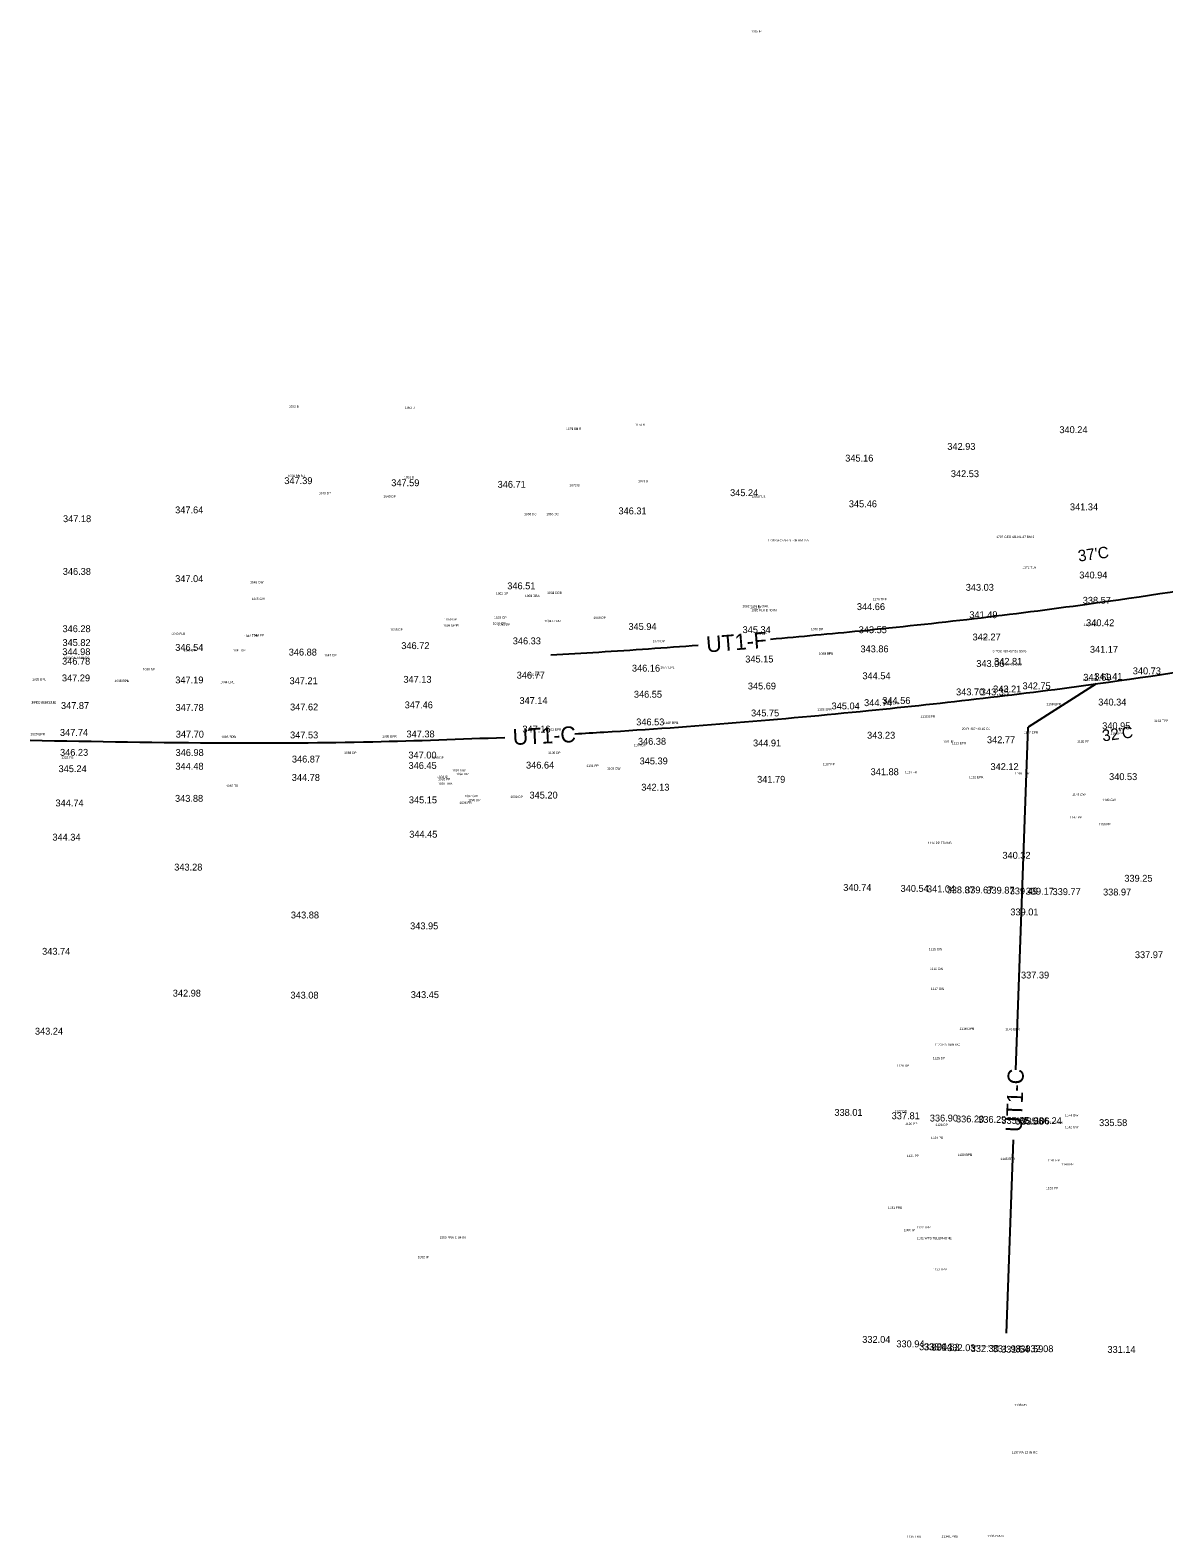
# Model space of a CAD drawing. Extents: x 49683 to 58852, y 49596 to 54801.
# Drawn here: x 50560 to 51054, y 49596 to 50254 of the extents above; entities that cross this region are included whole.
import ezdxf

# ---------------------------------------------------------------- set-up
doc = ezdxf.new("R2010")
doc.units = 0
for name, color, linetype in [('Level 2', 7, 'Continuous'), ('Level 32', 7, 'Continuous'), ('Level 48', 7, 'Continuous'), ('Level 51', 7, 'Continuous'), ('Level 53', 7, 'Continuous'), ('Level 56', 7, 'Continuous'), ('Level 58', 7, 'Continuous'), ('Level 59', 7, 'Continuous'), ('Level 61', 7, 'Continuous'), ('Level 62', 7, 'Continuous')]:
    doc.layers.add(name, color=color, linetype=linetype)

msp = doc.modelspace()

# ---------------------------------------------------------------- linework, layer by layer
at = {"layer": 'Level 2'}
for p, q in [((51025.02, 49968.44), (50995.33, 49949.54)), ((50989.95, 49800.05), (50995.33, 49949.54)), ((50985.82, 49685.22), (50988.85, 49769.48))]:
    msp.add_line(p, q, dxfattribs=at)
for points in [[(50882.95, 49988.03), (50922.2, 49991.68), (51021.03, 50003.3), (51093.49, 50014.19), (51156.12, 50024.93), (51216.22, 50037.32)], [(50787.09, 49981.18), (50808.05, 49982.38), (50851.37, 49985.39)], [(50797.5, 49946.69), (50810.2, 49947.44), (50925.67, 49956.85), (51025.68, 49968.6), (51099.51, 49979.7)], [(50559.97, 49943.89), (50644.94, 49942.73), (50709.41, 49943.24), (50766.95, 49945.13)]]:
    msp.add_spline(points, degree=3, dxfattribs=at)

# ---------------------------------------------------------------- texts
for s, rotation, p in [('UT1-F', 4.55325, (50855.13, 49982.17)), ('UT1-C', 2.65952, (50770.61, 49941.8)), ('UT1-C', 87.93828, (50992.47, 49772.85))]:
    msp.add_text(s, height=7, rotation=rotation, dxfattribs=at).set_placement(p)
at = {"layer": 'Level 32'}
for s, p in [('340.24', (51008.91, 50077.89)), ('342.93', (50960.03, 50070.59)), ('345.16', (50915.5, 50065.48)), ('347.39', (50670.83, 50055.65)), ('347.59', (50717.47, 50054.73)), ('346.71', (50763.88, 50054.05)), ('342.53', (50961.58, 50058.69)), ('345.24', (50865.28, 50050.4)), ('347.64', (50623.21, 50042.89)), ('346.31', (50816.58, 50042.47)), ('345.46', (50917.07, 50045.54)), ('341.34', (51013.52, 50044.21)), ('347.18', (50574.31, 50039.05)), ('346.38', (50574.2, 50016.05)), ('340.94', (51017.59, 50014.48)), ('347.04', (50623.23, 50012.89)), ('346.51', (50768.09, 50009.75)), ('343.03', (50968.07, 50009.11)), ('344.66', (50920.59, 50000.68)), ('338.57', (51019.11, 50003.45)), ('341.49', (50969.64, 49997.16)), ('346.28', (50574.08, 49991.05)), ('345.94', (50820.93, 49992.01)), ('345.34', (50870.73, 49990.64)), ('343.55', (50921.38, 49990.61)), ('342.27', (50971.05, 49987.44)), ('340.42', (51020.59, 49993.66)), ('344.98', (50573.98, 49981.03)), ('345.82', (50574.05, 49985.01)), ('346.54', (50623.26, 49982.89)), ('346.88', (50672.76, 49980.85)), ('346.72', (50721.86, 49983.66)), ('346.33', (50770.48, 49985.74)), ('343.86', (50922.14, 49982.24)), ('341.17', (51022.24, 49982.06)), ('346.78', (50573.89, 49976.87)), ('345.15', (50871.9, 49977.81)), ('343.06', (50972.67, 49975.85)), ('342.81', (50980.44, 49976.81)), ('347.29', (50573.83, 49969.57)), ('347.19', (50623.27, 49968.69)), ('347.21', (50673.12, 49968.35)), ('347.13', (50722.77, 49968.96)), ('346.77', (50772.2, 49970.78)), ('346.16', (50822.47, 49973.84)), ('344.54', (50922.99, 49970.51)), ('341.69', (51019.34, 49969.86)), ('341.41', (51024.17, 49970.24)), ('340.73', (51040.93, 49972.66)), ('346.55', (50823.31, 49962.45)), ('345.69', (50873.03, 49966.05)), ('343.70', (50963.85, 49963.47)), ('343.35', (50974.64, 49963.46)), ('343.21', (50980.03, 49964.75)), ('342.75', (50992.84, 49966.12)), ('347.87', (50573.41, 49957.52)), ('347.78', (50623.39, 49956.71)), ('347.62', (50673.34, 49956.89)), ('347.46', (50723.36, 49957.81)), ('347.14', (50773.39, 49959.71)), ('345.04', (50909.55, 49957.35)), ('344.74', (50923.73, 49958.78)), ('344.56', (50931.67, 49959.72)), ('340.34', (51025.87, 49959.04)), ('346.53', (50824.33, 49950.37)), ('345.75', (50874.42, 49954.28)), ('340.95', (51027.59, 49948.67)), ('347.74', (50572.97, 49945.78)), ('347.70', (50623.49, 49945.03)), ('347.53', (50673.34, 49944.69)), ('347.38', (50724.13, 49945.12)), ('347.16', (50774.68, 49947.26)), ('346.38', (50825.08, 49941.92)), ('343.23', (50925.03, 49944.57)), ('342.77', (50977.33, 49942.59)), ('346.23', (50573, 49937.1)), ('346.98', (50623.4, 49937.03)), ('347.00', (50724.97, 49935.93)), ('344.91', (50875.28, 49941.19)), ('345.24', (50572.36, 49929.97)), ('344.48', (50623.33, 49931.03)), ('346.87', (50674.14, 49934.17)), ('346.45', (50725.02, 49931.37)), ('346.64', (50776.27, 49931.53)), ('345.39', (50825.82, 49933.35)), ('341.88', (50926.58, 49928.64)), ('342.12', (50978.87, 49930.88)), ('344.78', (50674.09, 49926.14)), ('342.13', (50826.54, 49921.89)), ('341.79', (50877.07, 49925.34)), ('340.53', (51030.6, 49926.5)), ('344.74', (50571.02, 49915.03)), ('343.88', (50623.16, 49917.03)), ('345.15', (50725.16, 49916.37)), ('345.20', (50777.79, 49918.45)), ('344.34', (50569.67, 49900.09)), ('344.45', (50725.31, 49901.37)), ('340.32', (50984.07, 49892.18)), ('343.28', (50622.82, 49887.03)), ('339.25', (51037.25, 49882.15)), ('340.74', (50914.65, 49878.13)), ('340.54', (50939.65, 49877.73)), ('341.04', (50951.16, 49877.54)), ('338.87', (50959.74, 49877.08)), ('339.67', (50967.78, 49877.08)), ('339.87', (50977.07, 49876.94)), ('339.49', (50987.24, 49876.62)), ('339.17', (50994.24, 49876.51)), ('339.77', (51005.95, 49876.32)), ('338.97', (51027.96, 49876.16)), ('343.88', (50673.7, 49866.14)), ('339.01', (50987.53, 49867.47)), ('343.95', (50725.71, 49861.38)), ('343.74', (50565.19, 49850.29)), ('337.97', (51041.86, 49848.81)), ('337.39', (50992.18, 49839.94)), ('342.98', (50622.18, 49832.04)), ('343.08', (50673.48, 49831.14)), ('343.45', (50726.01, 49831.38)), ('343.24', (50562.05, 49815.43)), ('338.01', (50910.79, 49780)), ('337.81', (50935.75, 49778.53)), ('336.90', (50952.4, 49777.54)), ('336.20', (50963.82, 49777.13)), ('336.29', (50973.51, 49776.95)), ('335.85', (50983.62, 49776.51)), ('335.06', (50989.67, 49776.21)), ('335.06', (50992.41, 49776.24)), ('336.24', (50997.71, 49776.38)), ('335.58', (51026.25, 49775.53)), ('332.04', (50922.93, 49680.95)), ('330.94', (50937.8, 49679.02)), ('333.04', (50947.72, 49677.75)), ('333.04', (50949.71, 49677.68)), ('331.53', (50953.11, 49677.56)), ('332.03', (50960.03, 49677.33)), ('332.30', (50970.24, 49676.98)), ('331.98', (50979.85, 49676.89)), ('331.54', (50983.5, 49676.65)), ('330.59', (50989.63, 49676.82)), ('332.08', (50994.03, 49676.9)), ('331.14', (51029.88, 49676.58))]:
    msp.add_text(s, height=3, dxfattribs=at).set_placement(p)
at = {"layer": 'Level 48'}
for s, p in [("37'C", (51017.34, 50021.8)), ("32'C", (51027.86, 49943.34))]:
    msp.add_text(s, height=5, rotation=7.63667, dxfattribs=at).set_placement(p)
at = {"layer": 'Level 51'}
for s, p in [('3 POC 487+57.85 S576', (50979.8, 49982.24)), ('35 PI 10+00 SEC', (50981.8, 49976.57)), ('2 PC 483+37.15', (50560.55, 49959.84)), ('19 PC 483+37.15', (50560.55, 49959.84)), ('20 PI 487+43.15 C1', (50966.39, 49948.36)), ('36 POT 13+00 SEC', (50970.24, 49678.98))]:
    msp.add_text(s, height=1, dxfattribs=at).set_placement(p)
at = {"layer": 'Level 53'}
for s, p in [('1173 EPL', (51019.47, 49993.76)), ('1171 EPL', (50972.31, 49987.88)), ('1081 EPL', (50904, 49981.2)), ('1028 EPL', (50560.88, 49969.93)), ('1076 EPL', (50776.63, 49971.93)), ('1077 EPL', (50834.92, 49975.18)), ('1169 EPR', (51019.22, 49969.73)), ('1036 EPL', (50596.78, 49969.27)), ('1044 EPL', (50642.96, 49968.79)), ('1108 EPR', (50903.34, 49956.81)), ('1109 EPR', (50932.71, 49959.6)), ('1168 EPR', (51003.29, 49959.15)), ('1106 EPR', (50836.42, 49950.95)), ('1110 EPR', (50948.37, 49953.75)), ('1029 EPR', (50560.13, 49946.07)), ('1085 EPR', (50643.37, 49944.82)), ('1089 EPR', (50713.55, 49945.06)), ('1102 EPR', (50785.4, 49948.08)), ('1167 EPR', (50993.36, 49946.81)), ('1111 EPR', (50962, 49942.08)), ('1112 EPR', (50969.48, 49927.29)), ('1166 EPR', (50989.55, 49928.95)), ('1118 EPR', (50965.38, 49817.53)), ('1146 EPR', (50985.31, 49817.35)), ('1130 EPR', (50964.52, 49762.5)), ('1145 EPR', (50983.22, 49760.72)), ('1134 EPRB', (50957.52, 49596.01)), ('1136 EPRA', (50977.5, 49596.18))]:
    msp.add_text(s, height=1, dxfattribs=at).set_placement(p)
at = {"layer": 'Level 56'}
for s, p in [('1030 PA 18 IN RC', (50574.57, 49979.3)), ('1033 PB', (50573.55, 49935.83)), ('1123 PA 18IN RC', (50954.5, 49810.55)), ('1124 PB', (50952.91, 49769.9)), ('1138 PB', (50989.32, 49653.34)), ('1137 PA 12 IN RC', (50988.07, 49632.64))]:
    msp.add_text(s, height=1, dxfattribs=at).set_placement(p)
at = {"layer": 'Level 58'}
for s, p in [('1053 B', (50672.76, 50089.04)), ('1052 B', (50723.48, 50088.49)), ('1071 BA R', (50793.74, 50079.26)), ('1075 BB', (50793.74, 50079.26)), ('1074 B', (50823.68, 50081.09)), ('1050 BA BU', (50672.35, 50058.71)), ('1054 BB', (50672.35, 50058.71)), ('1051 B', (50723.07, 50058.16)), ('1073 B', (50825.18, 50056.49)), ('1048 DP', (50685.84, 50051.18)), ('1049 DP', (50714.1, 50049.77)), ('1072 B', (50795.24, 50054.66)), ('1084 FLB', (50874.68, 50049.7)), ('1065 DC', (50775.44, 50042.07)), ('1066 DC', (50785.12, 50042.07)), ('1062 DP', (50763.17, 50007.41)), ('1063 DP', (50775.82, 50006.4)), ('1064 DCA', (50775.82, 50006.4)), ('1068 DP', (50785.48, 50007.7)), ('1067 DCB', (50785.48, 50007.7)), ('1059 GPI', (50740.66, 49996.15)), ('1058 GPI', (50762.33, 49996.93)), ('1069 DP', (50805.7, 49996.84)), ('1083 FLA B 40 IN', (50874.52, 50000.14)), ('1040 FLB', (50621.59, 49989.84)), ('1055 DP', (50717.13, 49991.66)), ('1056 GPIA', (50740.1, 49993.52)), ('1060 GPIB', (50740.1, 49993.52)), ('1057 GPI', (50761.77, 49994.3)), ('1061 DP', (50763.96, 49993.94)), ('1078 DP', (50875.83, 49989.8)), ('1079 DP', (50900.54, 49991.88)), ('1070 DP', (50831.48, 49986.68)), ('1039 DP', (50626.91, 49982.72)), ('1041 DP', (50648.49, 49982.62)), ('1047 DP', (50688.19, 49980.45)), ('1080 DPB', (50904, 49981.2)), ('1038 DP', (50609.12, 49974.35)), ('1037 DPA', (50596.78, 49969.27)), ('1105 DPB', (50836.42, 49950.95)), ('1086 DPA', (50643.37, 49944.82)), ('1088 DP', (50696.95, 49937.91)), ('1100 DP', (50785.93, 49937.93)), ('1104 DP', (50823.2, 49941.23)), ('1090 DP', (50735.03, 49935.81)), ('1094 DP', (50745.78, 49928.66)), ('1113 FR', (50941.57, 49929.52)), ('1098 DP', (50751, 49917.3)), ('1099 DP', (50769.49, 49918.68)), ('1096 FR', (50747.24, 49916.1)), ('1119 DPA', (50965.38, 49817.53)), ('1126 DP', (50938, 49801.4)), ('1125 DP', (50953.7, 49804.65)), ('1127 DP', (50937.04, 49781.53)), ('1128 DP', (50954.87, 49775.56)), ('1129 DPB', (50964.52, 49762.5)), ('1131 FRB', (50934.14, 49739.39)), ('1095 FRA C 84 IN', (50738.59, 49726.46))]:
    msp.add_text(s, height=1, dxfattribs=at).set_placement(p)
at = {"layer": 'Level 59'}
for s, p in [('1046 GW', (50655.91, 50012.33)), ('1045 GW', (50656.57, 50005.07)), ('1170 TPP', (50927.48, 50004.9)), ('1042 TPP', (50653.27, 49988.89)), ('1043 PP', (50656.75, 49989.19)), ('1163 TPP', (51050.24, 49951.85)), ('1164 PP', (51031.23, 49946.38)), ('1165 PP', (51016.68, 49942.82)), ('1091 GW', (50744.04, 49930.26)), ('1101 PP', (50802.64, 49932.25)), ('1103 GW', (50811.63, 49931.05)), ('1107 PP', (50905.64, 49932.91)), ('1092 PP', (50737.94, 49926.44)), ('1097 GW', (50749.46, 49919.06)), ('1148 GW', (51014.53, 49919.71)), ('1149 GW', (51027.66, 49917.34)), ('1147 PP', (51013.46, 49909.75)), ('1150 PP', (51025.99, 49906.72)), ('1114 PP TRANS', (50951.52, 49898.57)), ('1115 GW', (50951.97, 49852.22)), ('1116 GW', (50952.37, 49843.64)), ('1117 GW', (50952.83, 49834.95)), ('1144 GW', (51011.34, 49779.68)), ('1120 PP', (50941.67, 49776.01)), ('1143 GW', (51004.65, 49776.49)), ('1142 GW', (51011.36, 49774.61)), ('1121 PP', (50942.35, 49762.02)), ('1141 PP', (51003.79, 49760.08)), ('1140 PP', (51009.85, 49758.34)), ('1139 PP', (51003.1, 49747.93)), ('1122 TPP', (50946.61, 49730.86)), ('1132 WTS TELEPHONE', (50946.66, 49726.14))]:
    msp.add_text(s, height=1, dxfattribs=at).set_placement(p)
at = {"layer": 'Level 61'}
for s, p in [('1172 TLA', (50992.78, 50018.8)), ('1082 T 24 IN OAK', (50870.67, 50001.9)), ('1093 TRB', (50737.94, 49924.44)), ('1087 TR', (50645.47, 49923.45)), ('1133 TRA', (50953.66, 49712.52)), ('1135 TRB', (50942.38, 49595.88))]:
    msp.add_text(s, height=1, dxfattribs=at).set_placement(p)
at = {"layer": 'Level 62'}
for s, p in [('1005 IP', (50874.29, 50252.71)), ('1708 GEO AB-NL-36 BM 2-A', (50881.6, 50030.62)), ('1707 GEO AB-NL-37 BM 2 ', (50981.38, 50032.12)), ('1012 IP', (50874.06, 50001.37)), ('1004 IP RR', (50784.3, 49995.42)), ('1001 IP', (50958.03, 49942.78)), ('1003 IP', (50737.47, 49927.38)), ('1000 IP', (50941.1, 49729.68)), ('1002 IP', (50729.08, 49717.87))]:
    msp.add_text(s, height=1, dxfattribs=at).set_placement(p)

doc.saveas('drawing.dxf')
